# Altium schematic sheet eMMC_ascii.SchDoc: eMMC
size A3; Date: Not used; ApprovedBy: Not used; CheckedBy: Not used; Author: Not used; CompanyName: STMicroelectronics; DrawnBy: Not used; Engineer: Not used; Organization: Not used; Address1: Not used; Address2: Not used; Address3: Not used; Address4: Not used; DocumentNumber: 7; Revision: Not used; SheetNumber: 7; SheetTotal: 7
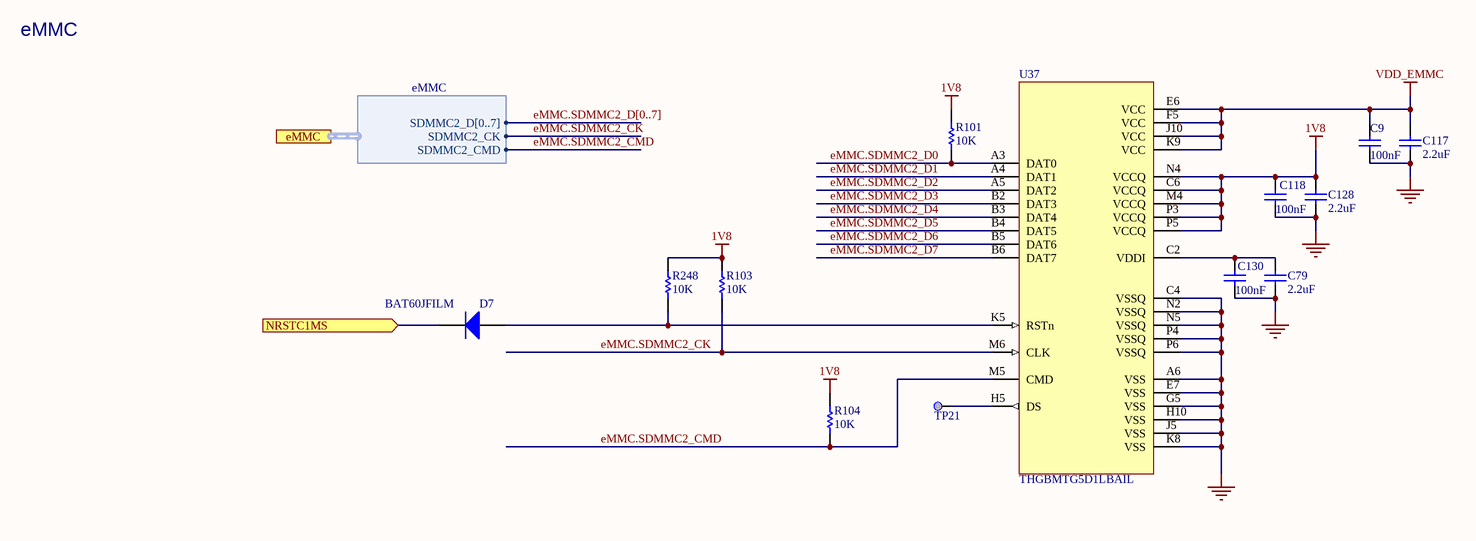
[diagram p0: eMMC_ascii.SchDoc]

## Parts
C9  value 100nF  [C0402]  (hidden comment: Capacitor)
C79  value 2.2uF  [C0402]  (hidden comment: Capacitor)
C117  value 2.2uF  [C0402]  (hidden comment: Capacitor)
C118  value 100nF  [C0402]  (hidden comment: Capacitor)
C128  value 2.2uF  [C0402]  (hidden comment: Capacitor)
C130  value 100nF  [C0402]  (hidden comment: Capacitor)
D7  BAT60JFILM  [DIO_SOD323]
R101  value 10K  [R0402]  (hidden comment: Resistor)
R103  value 10K  [R0402]  (hidden comment: Resistor)
R104  value 10K  [R0402]  (hidden comment: Resistor)
R248  value 10K  [R0402]  (hidden comment: Resistor)
TP21  Test Point  [TP_SMD_1MM]  (value not drawn)  (no BOM)
U37  value THGBMTG5D1LBAIL  [ICC_P-WFBGA153_13X11P5_P050]  (hidden comment: eMMC_THGBMTG5D1LBAIL)

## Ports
eMMC (harness eMMC), NRSTC1MS (in)

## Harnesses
eMMC: SDMMC2_CK, SDMMC2_CMD, SDMMC2_D[0..7]

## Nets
1V8: C118.2 C128.2 R101.2 R103.2 R104.2 R248.2 U37.C6(VCCQ) U37.M4(VCCQ) U37.N4(VCCQ) U37.P3(VCCQ) U37.P5(VCCQ)
GND: C9.1 C79.1 C117.1 C118.1 C128.1 C130.1 U37.A6(VSS) U37.C4(VSSQ) U37.E7(VSS) U37.G5(VSS) U37.H10(VSS) U37.J5(VSS) U37.K8(VSS) U37.N2(VSSQ) U37.N5(VSSQ) U37.P4(VSSQ) U37.P6(VSSQ)
VDD_EMMC: C9.2 C117.2 U37.E6(VCC) U37.F5(VCC) U37.J10(VCC) U37.K9(VCC)
eMMC.SDMMC2_CK: R103.1 U37.M6(CLK) ; port eMMC.SDMMC2_CK
eMMC.SDMMC2_CMD: R104.1 U37.M5(CMD) ; port eMMC.SDMMC2_CMD
eMMC.SDMMC2_D0: R101.1 U37.A3(DAT0)
eMMC.SDMMC2_D1: U37.A4(DAT1)
eMMC.SDMMC2_D2: U37.A5(DAT2)
eMMC.SDMMC2_D3: U37.B2(DAT3)
eMMC.SDMMC2_D4: U37.B3(DAT4)
eMMC.SDMMC2_D5: U37.B4(DAT5)
eMMC.SDMMC2_D6: U37.B5(DAT6)
eMMC.SDMMC2_D7: U37.B6(DAT7)
NRSTC1MS: D7.2(K) ; port NRSTC1MS
NetC79_2: C79.2 C130.2 U37.C2(VDDI)
NetD7_1: D7.1(A) R248.1 U37.K5(RSTn)
NetTP21_1: TP21.1 U37.H5(DS)

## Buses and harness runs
bus eMMC.SDMMC2_D[0..7]

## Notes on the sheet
- eMMC

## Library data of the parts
C9 C118 C130 = MCD-00006: Capacitor, MLCC, 100nF, 16V, X7R, +/-10%, 0402, T=0.5mm; Part_Preference: Recommended; Manufacturer: YAGEO; Manufacturer_Part_Number: CC0402KRX7R7BB104; Alternate_Manufacturer: MURATA; Alternate_Manufacturer_Part_Number: GCM155R71C104KA55D; Partial_Alternate_Internal_Part_Number: MCD-03299; Order_Code_RS: 616-9701; Component_Country_Of_Origin: China; Alternate_EMS: M; ID: 2474; ShowFields: YES
C79 C117 C128 = MCD-02606: Capacitor, MLCC, 2.2uF, 6.3V, X5R, +/-10%, 0402, T=0.5mm; Part_Preference: Recommended; Manufacturer: YAGEO; Manufacturer_Part_Number: CC0402KRX5R5BB225; Order_Code_RS: 1992205; ShowFields: YES; ID: 4712; Component_Country_Of_Origin: China°
D7 = MCD-00034: BMS_Part_Number: 9151097; Part_Type: Diode; Part_Preference: Recommended; Manufacturer: STMICROELECTRONICS; Manufacturer_HQ_COO: EU; Component_Country_Of_Origin: China; ShowFields: YES; ID: 2483
R101 R103 R104 R248 = MCD-00053: Resistor,10K,0402,1%,1/16W; Manufacturer_Part_Number: RC0402FR-0710KL; Manufacturer: YAGEO; BMS_Part_Number: 9131590; Part_Preference: Recommended; ECCN_US: EAR99; ECCN_EU: NEC; Provided_By: SUBCO; Component_Country_Of_Origin: China; ID: 2539; ShowFields: YES
TP21 = MCD-00074: Test Point 1mm; Part_Type: Misc; Part_Preference: Recommended; ID: 2518; ShowFields: YES
U37 = MCD-02799: Memory, eMMC, 4GB, 15nm ,WFBGA , 153 pins; Part_Type: IC; Part_Preference: Recommended; Manufacturer: KIOXIA; ShowFields: YES; ID: 4911; Component_Country_Of_Origin: Unknown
